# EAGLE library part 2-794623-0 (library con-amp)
MICRO MATE N LOK Dual Row, grid 1.5 mm Source: http://catalog.tycoelectronics.com .. ENG_CD_794623_F.pdf
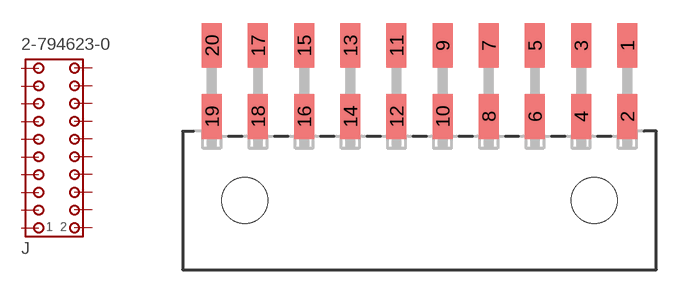
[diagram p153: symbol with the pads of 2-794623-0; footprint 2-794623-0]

Designator prefix J

## 2-794623-0 (MF: TYCO ELECTRONICS; MPN: 2-794623-0; OC_FARNELL: unknown; OC_NEWARK: 15H4155)  [2-794623-0]
1  1  pas
2  2  pas
3  3  pas
4  4  pas
5  5  pas
6  6  pas
7  7  pas
8  8  pas
9  9  pas
10  10  pas
11  11  pas
12  12  pas
13  13  pas
14  14  pas
15  15  pas
16  16  pas
17  17  pas
18  18  pas
19  19  pas
20  20  pas

## Footprint 2-794623-0 (pad centres in mm)
MICRO MATE N LOK Dual Row, grid 1.5 mm Source: http://catalog.tycoelectronics.com .. ENG_CD_794623_F.pdf
smd 1.3 x 2.92: 1 13.5,10.1; 2 13.5,5.48; 3 10.5,10.1; 4 10.5,5.48; 5 7.5,10.1; 6 7.5,5.48; 7 4.5,10.1; 8 4.5,5.48; 9 1.5,10.1; 10 1.5,5.48; 11 -1.5,10.1; 12 -1.5,5.48; 13 -4.5,10.1; 14 -4.5,5.48; 15 -7.5,10.1; 16 -7.5,5.48; 17 -10.5,10.1; 18 -10.5,5.48; 19 -13.5,5.48; 20 -13.5,10.1
hole 3 at -11.35,0
hole 3 at 11.35,0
